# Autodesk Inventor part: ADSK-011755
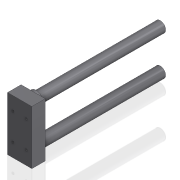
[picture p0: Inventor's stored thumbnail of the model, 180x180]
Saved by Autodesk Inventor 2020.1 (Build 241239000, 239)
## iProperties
Created: 1999-11
Part Number: ADSK-011755
Material: Acier doux
Document SubType Name: Modeling
Designer: sspink
Density: 7.86 g/cm^3
Appearance: Metal-Steel(Polish)
Mass: 2054.82 g
Surface Area: 475.189 cm^2
Volume: 261.427 cm^3
Control State: 0
Master: False
Checked Out: False
Shininess: 0.0
Length Units: 11269
Angle Units: 11279
Time Units: 11290
Mass Units: 11283
Length Display Precision: 3
Angle Display Precision: 2
Compacted: True
Dimensions: 45x100x261 mm
Mass: 2,055 kg
Density: 0.0
Volumn: 0.0
Area: 0.0
PropertySet Name: Model Information
Author: sspink
Revision Number: -
Title: ADSK-011755
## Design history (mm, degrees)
workplane "Work Plane1"
node "Solide1"
  node "Extrusion1" dims "d2" = 25 (= O), "d3" = 0
  node "Extrusion2" dims "d7" = 236 (= Shaft), "d8" = 0
  node "Extrusion3" dims "d10" = 5.5 (= P - O), "d11" = 0
  node "Hole1" dims "d20" = 4.917, "d21" = 9.525, "d22" = 6.35, "d23" = 60 deg, "d24" = 17.1, "d25" = 118 deg, "d29" = 12
sketch "Sketch1"
  geometry: L1 (-21.899, 58.729)-(23.101, 58.729) reference; L2 (23.101, 58.729)-(23.101, -41.271); L3 (23.101, -41.271)-(-21.899, -41.271); L4 (-21.899, -41.271)-(-21.899, 58.729) reference
  constraints: 8 end point, 2 horizontal, 2 parallel, 1 perpendicular, 1 vertical
  dimensions: "d0" = 100 distance of L3.end L1.start (= F); "d1" = 45 distance of L1.start L1.end (= H)
sketch "Sketch4"
  geometry: L1 (-21.899, 58.729)-(23.101, 58.729) reference; L2 (-21.899, -41.271)-(-21.899, 58.729) reference; L3 (23.101, -41.271)-(-21.899, -41.271) reference; L4 (23.101, 58.729)-(23.101, -41.271) reference; L5 (0.601, 58.729)-(0.601, -41.271); L6 (-21.899, 8.729)-(23.101, 8.729); 4 further points
  constraints: 4 end point, 4 midpoint
  dimensions: "d12" = 25 distance from line of point (13.101, 33.729) L6 (= 0.5 x E0); "d13" = 25 distance from line of point (-11.899, 33.729) L6 (= 0.5 x E0); "d14" = 25 distance from line of point (13.101, -16.271) L6 (= 0.5 x E0); "d15" = 25 distance from line of L6 point (-11.899, -16.271) (= 0.5 x E0); "d17" = 12.5 distance from line of L5 point (-11.899, 33.729) (= 0.5 x G); "d18" = 12.5 distance from line of point (-11.899, -16.271) L5 (= 0.5 x G); "d26" = 25 distance of point (-11.899, 33.729) point (13.101, 33.729) (= G); "d27" = 25 distance of point (-11.899, -16.271) point (13.101, -16.271) (= G)
node "Corps solides"
node "Corps surfaciques"
sketch "Sketch2"
  geometry: L1 (21.899, 58.729)-(21.899, -41.271) reference; L2 (-23.101, 58.729)-(21.899, 58.729) reference; L3 (-23.101, -41.271)-(-23.101, 58.729) reference; L4 (21.899, -41.271)-(-23.101, -41.271) reference; L5 (-0.601, 58.729)-(-0.601, -41.271); L6 (-23.101, 8.729)-(21.899, 8.729); C1 r 10 at (-0.601, 45.229); C2 r 10 at (-0.601, -27.771)
  constraints: 4 end point, 4 midpoint, 2 centre point, 2 point on line, 1 equal radius
  dimensions: "d4" = 36.5 distance from line of C1.centre L6 (= 0.5 x W0); "d5" = 36.5 distance from line of L6 C2.centre (= 0.5 x W0); "d6" = 20 diameter of C1 (= X)
sketch "Sketch3"
  geometry: C1 r 10 at (-0.601, 45.229) reference; C2 r 10 at (-0.601, -27.771) reference; C3 r 13.175 at (-0.601, 45.229); C4 r 13.175 at (-0.601, -27.771)
  constraints: 2 centre point, 2 coincident, 1 equal radius
  dimensions: "d9" = 26.35 diameter of C4 (computed from X)
other parameters: "d16" = 6.35, "A" = 56 [user parameter; used in 1 equation term], "C" = 25 [user parameter], "D" = 25 [user parameter], "H" = 45 [user parameter; used in 1 equation term], "O" = 25 [user parameter; used in 3 equation terms], "P" = 30.5 [user parameter; used in 2 equation terms], "U" = 22.5 [user parameter; used in 1 equation term], "W0" = 73 [user parameter; used in 2 equation terms], "X" = 20 [user parameter; used in 2 equation terms], "Travel" = 76 [user parameter; used in 1 equation term], "F" = 100 [user parameter; used in 1 equation term], "Shaft" = 236 (= A + 2 x Travel + P - O + U) [user parameter; used in 1 equation term], "G" = 25 [user parameter; used in 4 equation terms], "d28" = -50.0126
